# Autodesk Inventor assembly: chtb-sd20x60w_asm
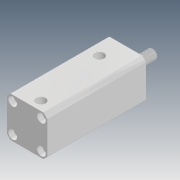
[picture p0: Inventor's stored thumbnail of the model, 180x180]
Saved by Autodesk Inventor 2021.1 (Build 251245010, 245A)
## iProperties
Company: Microsoft
Created: 2018-05
Part Number: chtb-sd20x60w_asm
Description: STEP AP214
Document SubType Name: Assembly
Designer: user
Title: chtb-sd20x60w_asm.STEP
Author: Windows
Revision Number: ÈÎºÎ
Sending System: SolidWorks 2015
Preprocessor: SwSTEP 2.0
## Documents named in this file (4)
- D:\Vault_2016\Projekty\Clamptek\Hydraulic\CHTB\CHTB-20\Inventor\CHTB-SD20x60W\chtb-sd20x60w_asm.iam
- D:\Vault_2016\Projekty\Clamptek\Hydraulic\CHTB\CHTB-20\Inventor\CHTB-SD20x60W\CHTB-SD20X60NBT.ipt
- D:\Vault_2016\Projekty\Clamptek\Hydraulic\CHTB\CHTB-20\Inventor\CHTB-SD20x60W\CHTB-SD20X60WHSG.ipt
- D:\Vault_2016\Projekty\Clamptek\Hydraulic\CHTB\CHTB-20\Inventor\CHTB-SD20x60W\QG.ipt
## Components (3 placed, 3 different names)
1. CHTB-SD20X60NBT_1
2. CHTB-SD20X60WHSG_2
3. QG_3
